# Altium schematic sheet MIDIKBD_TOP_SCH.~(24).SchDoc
size A4
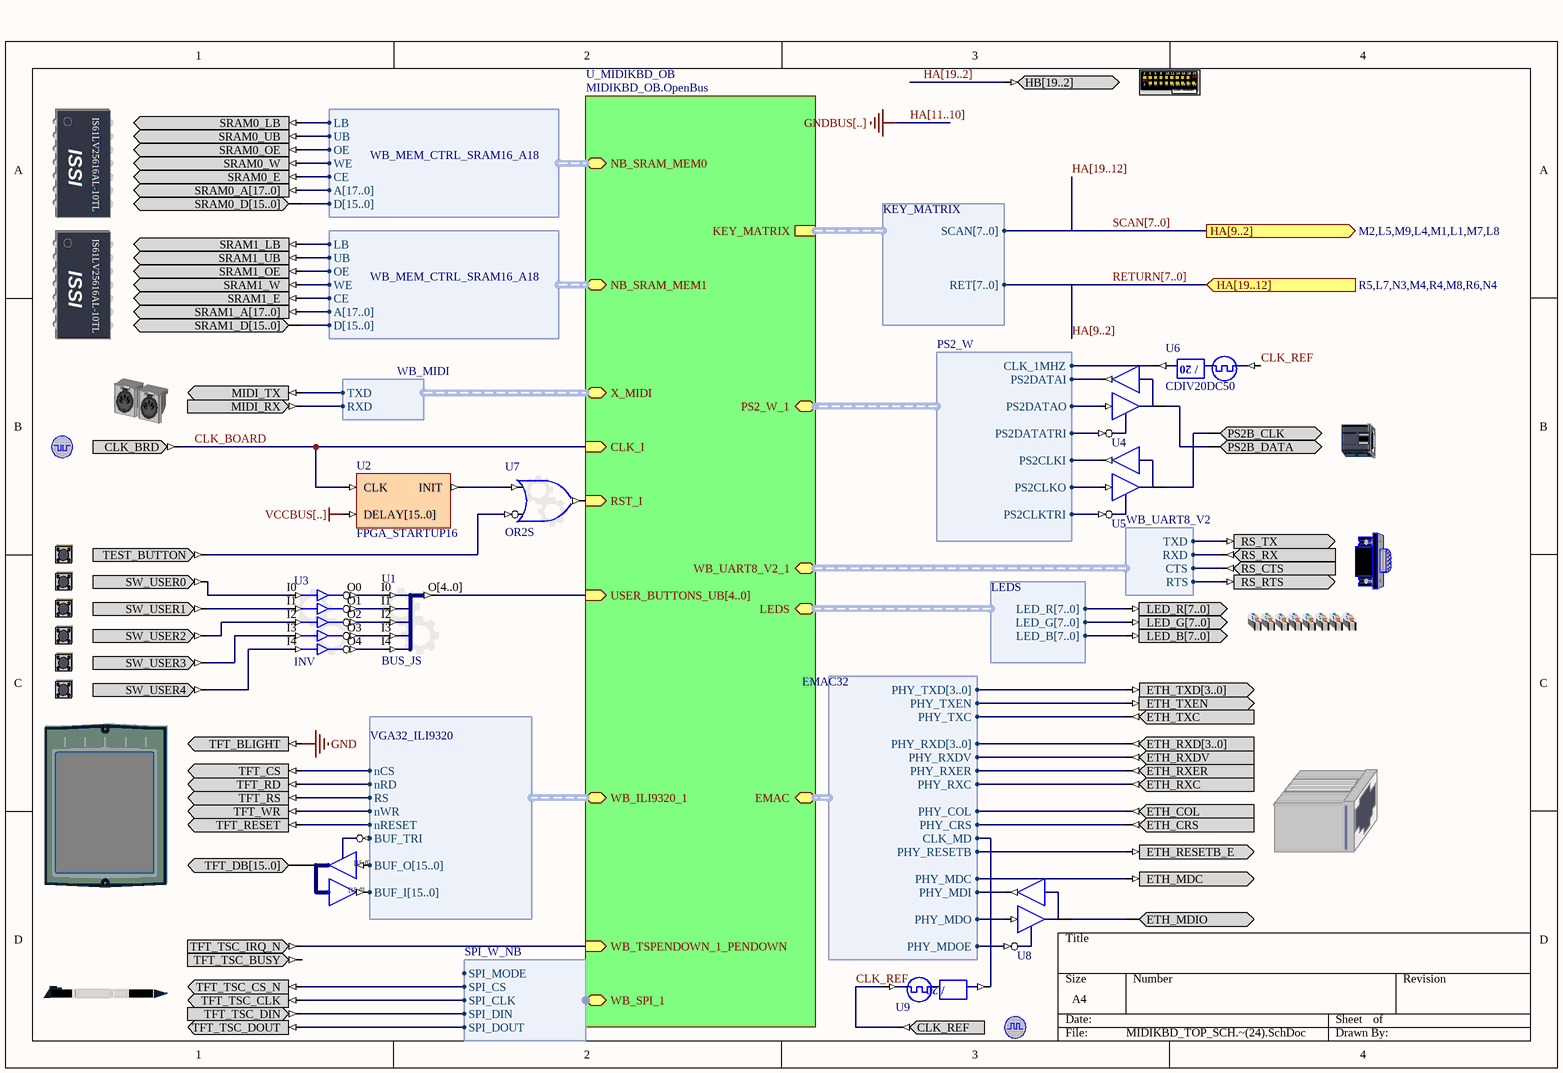
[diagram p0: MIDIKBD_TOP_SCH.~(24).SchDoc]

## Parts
(Parts that share a designator on the sheet are numbered #1, #2 ... from top to bottom, then left to right.)
?#1  USER_HEADER_B  (value not drawn)
?#2  SRAM0  (value not drawn)
?#3  SRAM1  (value not drawn)
?#4  MIDI  (value not drawn)
?#5  PS2B  (value not drawn)
?#6  CLOCK_BOARD  (value not drawn)
?#7  RS232CNTR  (value not drawn)
?#8  TEST_BUTTON  (value not drawn)
?#9  USER_BUTTON0  (value not drawn)
?#10  USER_BUTTON1  (value not drawn)
?#11  LEDS_RGB  (value not drawn)
?#12  USER_BUTTON2  (value not drawn)
?#13  USER_BUTTON3  (value not drawn)
?#14  USER_BUTTON4  (value not drawn)
?#15  ETH_PHY  (value not drawn)
?#16  TFT_LCD  (value not drawn)
?#17  TOUCH_SCREEN_PEN  (value not drawn)
?#18  CLOCK_REFERENCE  (value not drawn)
TFT_IOBUF  IOBUF16B  (value not drawn)
U1  BUS_JS
U2  FPGA_STARTUP16
U3  INV
U4  IOBUF  (value not drawn)
U5  IOBUF  (value not drawn)
U6  CDIV20DC50
U7  OR2S
U8  IOBUF  (value not drawn)
U9  CDIV20DC50  (value not drawn)

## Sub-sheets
U_MIDIKBD_OB = MIDIKBD_OB.OpenBus: KEY_MATRIX (harness KEY_MATRIX), RST_I (in), CLK_I (in), LEDS (harness LEDS), X_MIDI (harness WB_MIDI), USER_BUTTONS_UB[4..0] (in), NB_SRAM_MEM0 (harness WB_MEM_CTRL_SRAM16_A18), NB_SRAM_MEM1 (harness WB_MEM_CTRL_SRAM16_A18), PS2_W_1 (harness PS2_W), WB_ILI9320_1 (harness VGA32_ILI9320), EMAC (harness EMAC32), WB_TSPENDOWN_1_PENDOWN (in), WB_SPI_1 (harness SPI_W_NB), WB_UART8_V2_1 (harness WB_UART8_V2)

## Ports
HA[9..2] (out, see M2,L5,M9,L4,M1,L1,M7,L8), HA[19..12] (in, see R5,L7,N3,M4,R4,M8,R6,N4)

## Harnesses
KEY_MATRIX: SCAN[7..0], RET[7..0]
LEDS: LED_R[7..0], LED_G[7..0], LED_B[7..0]
WB_MIDI: RXD, TXD
WB_MEM_CTRL_SRAM16_A18: D[15..0], A[17..0], CE, WE, OE, UB, LB
PS2_W: PS2CLKTRI, PS2CLKO, PS2CLKI, PS2DATATRI, PS2DATAO, PS2DATAI, CLK_1MHZ
VGA32_ILI9320: BUF_TRI, BUF_O[15..0], BUF_I[15..0], nRESET, nWR, RS, nRD, nCS
EMAC32: PHY_TXD[3..0], PHY_TXEN, PHY_TXC, PHY_RXD[3..0], PHY_RXDV, PHY_RXER, PHY_RXC, PHY_COL, PHY_CRS, PHY_RESETB, PHY_MDC, PHY_MDOE, PHY_MDO, PHY_MDI, CLK_MD
SPI_W_NB: SPI_DOUT, SPI_DIN, SPI_CLK, SPI_CS, SPI_MODE
WB_UART8_V2: TXD, RXD, CTS, RTS

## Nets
GND: ?#16.TFT_BLIGHT
VCCBUS[..]: U2.DELAY[15..0]
CLK_BOARD: ?#6.CLK_BRD U2.CLK ; sheet U_MIDIKBD_OB/CLK_I
CLK_REF: ?#18.CLK_REF U6.CLKIN U9.CLKIN
Net?#2_SRAM0_E: ?#2.SRAM0_E ; sheet U_MIDIKBD_OB/NB_SRAM_MEM0.CE
Net?#2_SRAM0_LB: ?#2.SRAM0_LB ; sheet U_MIDIKBD_OB/NB_SRAM_MEM0.LB
Net?#2_SRAM0_OE: ?#2.SRAM0_OE ; sheet U_MIDIKBD_OB/NB_SRAM_MEM0.OE
Net?#2_SRAM0_UB: ?#2.SRAM0_UB ; sheet U_MIDIKBD_OB/NB_SRAM_MEM0.UB
Net?#2_SRAM0_W: ?#2.SRAM0_W ; sheet U_MIDIKBD_OB/NB_SRAM_MEM0.WE
Net?#3_SRAM1_E: ?#3.SRAM1_E ; sheet U_MIDIKBD_OB/NB_SRAM_MEM1.CE
Net?#3_SRAM1_LB: ?#3.SRAM1_LB ; sheet U_MIDIKBD_OB/NB_SRAM_MEM1.LB
Net?#3_SRAM1_OE: ?#3.SRAM1_OE ; sheet U_MIDIKBD_OB/NB_SRAM_MEM1.OE
Net?#3_SRAM1_UB: ?#3.SRAM1_UB ; sheet U_MIDIKBD_OB/NB_SRAM_MEM1.UB
Net?#3_SRAM1_W: ?#3.SRAM1_W ; sheet U_MIDIKBD_OB/NB_SRAM_MEM1.WE
Net?#4_MIDI_RX: ?#4.MIDI_RX ; sheet U_MIDIKBD_OB/X_MIDI.RXD
Net?#4_MIDI_TX: ?#4.MIDI_TX ; sheet U_MIDIKBD_OB/X_MIDI.TXD
Net?#5_PS2B_CLK: ?#5.PS2B_CLK U5.IO
Net?#5_PS2B_DATA: ?#5.PS2B_DATA U4.IO
Net?#7_RS_CTS: ?#7.RS_CTS ; sheet U_MIDIKBD_OB/WB_UART8_V2_1.CTS
Net?#7_RS_RTS: ?#7.RS_RTS ; sheet U_MIDIKBD_OB/WB_UART8_V2_1.RTS
Net?#7_RS_RX: ?#7.RS_RX ; sheet U_MIDIKBD_OB/WB_UART8_V2_1.RXD
Net?#7_RS_TX: ?#7.RS_TX ; sheet U_MIDIKBD_OB/WB_UART8_V2_1.TXD
Net?#8_TEST_BUTTON: ?#8.TEST_BUTTON U7.I1
Net?#9_SW_USER0: ?#9.SW_USER0 U3.I0
Net?#10_SW_USER1: ?#10.SW_USER1 U3.I1
Net?#12_SW_USER2: ?#12.SW_USER2 U3.I2
Net?#13_SW_USER3: ?#13.SW_USER3 U3.I3
Net?#14_SW_USER4: ?#14.SW_USER4 U3.I4
Net?#15_ETH_COL: ?#15.ETH_COL ; sheet U_MIDIKBD_OB/EMAC.PHY_COL
Net?#15_ETH_CRS: ?#15.ETH_CRS ; sheet U_MIDIKBD_OB/EMAC.PHY_CRS
Net?#15_ETH_MDC: ?#15.ETH_MDC ; sheet U_MIDIKBD_OB/EMAC.PHY_MDC
Net?#15_ETH_MDIO: ?#15.ETH_MDIO U8.IO
Net?#15_ETH_RESETB_E: ?#15.ETH_RESETB_E ; sheet U_MIDIKBD_OB/EMAC.PHY_RESETB
Net?#15_ETH_RXC: ?#15.ETH_RXC ; sheet U_MIDIKBD_OB/EMAC.PHY_RXC
Net?#15_ETH_RXDV: ?#15.ETH_RXDV ; sheet U_MIDIKBD_OB/EMAC.PHY_RXDV
Net?#15_ETH_RXER: ?#15.ETH_RXER ; sheet U_MIDIKBD_OB/EMAC.PHY_RXER
Net?#15_ETH_TXC: ?#15.ETH_TXC ; sheet U_MIDIKBD_OB/EMAC.PHY_TXC
Net?#15_ETH_TXEN: ?#15.ETH_TXEN ; sheet U_MIDIKBD_OB/EMAC.PHY_TXEN
Net?#16_TFT_CS: ?#16.TFT_CS ; sheet U_MIDIKBD_OB/WB_ILI9320_1.nCS
Net?#16_TFT_DB[15..0]: ?#16.TFT_DB[15..0] TFT_IOBUF.IO[15..0]
Net?#16_TFT_RD: ?#16.TFT_RD ; sheet U_MIDIKBD_OB/WB_ILI9320_1.nRD
Net?#16_TFT_RESET: ?#16.TFT_RESET ; sheet U_MIDIKBD_OB/WB_ILI9320_1.nRESET
Net?#16_TFT_RS: ?#16.TFT_RS ; sheet U_MIDIKBD_OB/WB_ILI9320_1.RS
Net?#16_TFT_WR: ?#16.TFT_WR ; sheet U_MIDIKBD_OB/WB_ILI9320_1.nWR
Net?#17_TFT_TSC_CLK: ?#17.TFT_TSC_CLK ; sheet U_MIDIKBD_OB/WB_SPI_1.SPI_CLK
Net?#17_TFT_TSC_CS_N: ?#17.TFT_TSC_CS_N ; sheet U_MIDIKBD_OB/WB_SPI_1.SPI_CS
Net?#17_TFT_TSC_DIN: ?#17.TFT_TSC_DIN ; sheet U_MIDIKBD_OB/WB_SPI_1.SPI_DIN
Net?#17_TFT_TSC_DOUT: ?#17.TFT_TSC_DOUT ; sheet U_MIDIKBD_OB/WB_SPI_1.SPI_DOUT
Net?#17_TFT_TSC_IRQ_N: ?#17.TFT_TSC_IRQ_N ; sheet U_MIDIKBD_OB/WB_TSPENDOWN_1_PENDOWN
NetTFT_IOBUF_T: TFT_IOBUF.T ; sheet U_MIDIKBD_OB/WB_ILI9320_1.BUF_TRI
NetU1_I0: U1.I0 U3.O0
NetU1_I1: U1.I1 U3.O1
NetU1_I2: U1.I2 U3.O2
NetU1_I3: U1.I3 U3.O3
NetU1_I4: U1.I4 U3.O4
NetU2_INIT: U2.INIT U7.I0
NetU4_I: U4.I ; sheet U_MIDIKBD_OB/PS2_W_1.PS2DATAO
NetU4_O: U4.O ; sheet U_MIDIKBD_OB/PS2_W_1.PS2DATAI
NetU4_T: U4.T ; sheet U_MIDIKBD_OB/PS2_W_1.PS2DATATRI
NetU5_I: U5.I ; sheet U_MIDIKBD_OB/PS2_W_1.PS2CLKO
NetU5_O: U5.O ; sheet U_MIDIKBD_OB/PS2_W_1.PS2CLKI
NetU5_T: U5.T ; sheet U_MIDIKBD_OB/PS2_W_1.PS2CLKTRI
NetU6_CLKDV: U6.CLKDV ; sheet U_MIDIKBD_OB/PS2_W_1.CLK_1MHZ
NetU7_O: U7.O ; sheet U_MIDIKBD_OB/RST_I
NetU8_I: U8.I ; sheet U_MIDIKBD_OB/EMAC.PHY_MDO
NetU8_O: U8.O ; sheet U_MIDIKBD_OB/EMAC.PHY_MDI
NetU8_T: U8.T ; sheet U_MIDIKBD_OB/EMAC.PHY_MDOE
NetU9_CLKDV: U9.CLKDV ; sheet U_MIDIKBD_OB/EMAC.CLK_MD

Not connected (* = marked no-connect by the designer): ?#1 HB[19..2]; ?#2 SRAM0_A[17..0] SRAM0_D[15..0]; ?#3 SRAM1_A[17..0] SRAM1_D[15..0]; ?#11 LED_B[7..0] LED_G[7..0] LED_R[7..0]; ?#15 ETH_RXD[3..0] ETH_TXD[3..0]; ?#17 TFT_TSC_BUSY; TFT_IOBUF I[15..0] O[15..0]; U1 O[4..0]

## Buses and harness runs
bus HA[9..2] = RETURN[7..0] = port HA[19..12]
bus HA[11..10]
bus HA[19..2]
bus HA[19..12] = SCAN[7..0] = port HA[9..2]

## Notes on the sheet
- Labels drawn without touching a wire or pin: GNDBUS[..]

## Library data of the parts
?#1 = USER_HEADER_B: User Header B; PortComponent: True
?#2 = SRAM0: Free Static RAM - Daughterboard; PortComponent: True
?#3 = SRAM1: Free Static RAM - Daughterboard; PortComponent: True
?#4 = MIDI: MIDI Connector; PortComponent: True
?#5 = PS2B: Key Board PS2 Connector; PortComponent: True
?#6 = CLOCK_BOARD: Global System Clock Supply; PortComponent: True
?#7 = RS232CNTR: DCE Serial Port Connector; PortComponent: True
?#8 = TEST_BUTTON: Test / Reset Button; PortComponent: True
?#9 = USER_BUTTON0: Generic User Button; PortComponent: True
?#10 = USER_BUTTON1: Generic User Button; PortComponent: True
?#11 = LEDS_RGB: LEDS RGB; PortComponent: True
?#12 = USER_BUTTON2: Generic User Button; PortComponent: True
?#13 = USER_BUTTON3: Generic User Button; PortComponent: True
?#14 = USER_BUTTON4: Generic User Button; PortComponent: True
?#15 = ETH_PHY: Ethernet PHY-interface; PortComponent: True
?#16 = TFT_LCD: TFT LCD Panel; PortComponent: True
?#17 = TFT_PEN: Touch Screen Pen Control; PortComponent: True
?#18 = CLOCK_REFERENCE: Global System Clock Reference Supply; PortComponent: True
TFT_IOBUF = IOBUF16B: 16-Bit Input/Output Buffer, Bus Version; SubClass: IOBUF; Enable: Low; Control: Common Control T; PortSize: 16; ArchiveName: GENERIC; VHDLIB_SIM: GENERIC_LIB
U1 = BUS_JS: Configurable Bus Joiner/Splitter; ConfiguratorName: GENERIC_BUS_JS; ConfigurationParameters: {}Version[1.1]{}SplitterJoinerType[Joiner]{}SignalCount[5]{}SignalWidth0[1]{}GapBelow0[1000000]{}ConnectionType0[Pin]{}SignalWidth1[1]{}GapBelow1[1000000]{}ConnectionType1[Pin]{}SignalWidth2[1]{}GapBelow2[1000000]{}ConnectionType2[Pin]{}SignalWidth3[1]{}GapBelow3[1000000]{}ConnectionType3[Pin]{}SignalWidth4[1]{}GapBelow4[1000000]{}ConnectionType4[Pin]{}ShowPinNames[True]{}
U2 = FPGA_STARTUP16: FPGA Startup With 16 Bit Delay
U3 = INV: Configurable Inverter; ConfigurationParameters: {}Version[1.1]{}SignalCount[5]{}SignalWidth0[1]{}OutputOption0[Inverted]{}SignalWidth1[1]{}OutputOption1[Inverted]{}SignalWidth2[1]{}OutputOption2[Inverted]{}SignalWidth3[1]{}OutputOption3[Inverted]{}SignalWidth4[1]{}OutputOption4[Inverted]{}EnableMode[None]{}ShowPinNames[True]{}; ConfiguratorName: GENERIC_BUFFER
U4 U5 = IOBUF: Input/Output Buffer; Enable: Low; Control: Common Control T; ArchiveName: GENERIC; VHDLIB_SIM: GENERIC_LIB
U6 U9 = CDIV20DC50: Clock Divider by 20 with 50% Duty Cycle Output; DivisorRate: 20; DutyCycle: 50; ArchiveName: GENERIC; VHDLIB_SIM: GENERIC_LIB
U7 = GATE: Configurable Generic Gate; ConfiguratorName: GENERIC_GATE; ConfigurationParameters: {}Version[1.0]{}GateKind[OR]{}BusInput[False]{}GateInputType[Bit]{}GateOutputOption[Normal]{}BusWidth[8]{}RegisterOutputs[False]{}NegativeClockEdge[False]{}InputCount[2]{}InputInvert0[False]{}InputInvert1[True]{}
U8 = iobuf: Input/Output Buffer; Enable: Low; Control: Common Control T; ArchiveName: GENERIC; VHDLIB_SIM: GENERIC_LIB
